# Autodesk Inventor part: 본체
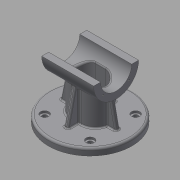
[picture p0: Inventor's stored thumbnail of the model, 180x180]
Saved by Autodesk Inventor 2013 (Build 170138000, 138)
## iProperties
Created: 2015-12
Part Number: 본체
Material: 일반
Document SubType Name: Modeling
Designer: mduedu
Density: 2.71 g/cm^3
Author: mduedu
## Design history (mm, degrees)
sketch "스케치1"
  geometry: L1 (45, 40)-(-45, 40); L2 (-45, 40)-(-45, -40); L3 (-45, -40)-(45, -40); L4 (45, -40)-(45, 40); L5 (45, 40)-(-45, -40); L6 (-45, 40)-(45, -40); 2 further points
  constraints: 12 end point, 2 midpoint, 2 parallel, 1 coincident, 1 horizontal, 1 perpendicular, 3 other
  dimensions: "d0" = 90 distance of L2.end L3.end; "d2" = 80 distance of L1.end L2.end
extrude "돌출1" new body sketch "스케치1" distance "d3" = 10; taper "d4" = 0 deg
sketch "스케치2"
  geometry: C1 r 32.5 at (80, 0); 1 further point
  constraints: 1 centre point
  dimensions: "d5" = 65 diameter of C1; "d116" = 80 distance of point (0, 0) C1.centre
extrude "돌출2" join sketch "스케치2" stored distance "d7" = 75; taper "d8" = 0 deg
sketch "스케치3"
  geometry: L1 (-27.5, -20)-(27.5, -20); L2 (27.5, -20)-(27.5, 20); L3 (27.5, 20)-(-27.5, 20); L4 (-27.5, 20)-(-27.5, -20); L5 (-27.5, -20)-(27.5, 20); L6 (27.5, -20)-(-27.5, 20); 1 further point
  constraints: 12 end point, 2 midpoint, 2 parallel, 1 horizontal, 1 perpendicular
  dimensions: "d9" = 55 distance of L2.end L3.end; "d11" = 40 distance of L1.end L2.end
extrude "돌출3" new body sketch "스케치3" stored distance "d12" = 75; taper "d13" = 0 deg
fillet "모깎기1"
fillet "모깎기2"
feature "결합1"
  node "솔리드2"
sketch "스케치4"
  geometry: L1 (-37.5, 47.5)-(37.5, 47.5) reference; L2 (32.5, 47.5)-(40.208, 10); L3 (37.5, 47.5)-(37.5, 112.5) reference; L4 (60.208, 0)-(60.208, 10) reference; L5 (60.208, 10)-(-60.208, 10) reference; 1 further point
  constraints: 2 end point, 2 point on line
  dimensions: "d15" = 5 distance from line of L2.start L3; "d117" = 20 distance from line of L2.end L4
sketch "스케치5"
  geometry: L1 (10, 35.208)-(58.179, 24.085); L2 (0, 60.208)-(10, 60.208) reference; L3 (10, -60.208)-(10, 60.208) reference; 2 further points
  constraints: 2 end point, 1 point on line, 2 other
  dimensions: "d118" = 25 distance from line of L1.start L2; "d119" = 77 deg angle of L1 L3
feature "리브1" dims "d19" = 1, "d20" = 6, "d21" = 0, "d22" = 0, "d23" = 1, "d24" = 1
feature "리브2" dims "d25" = 1, "d26" = 6, "d27" = 0, "d28" = 0, "d29" = 1, "d30" = 1
fillet "모깎기4" dims "d31" = 2
fillet "모깎기5" dims "d32" = 2
fillet "모깎기16" dims "d149" = 2
sketch "스케치6"
  geometry: L1 (0, 0)-(-32.88, 32.88); L2 (0, 0)-(-46.5, 0); A1 r 46.5 centre (0, 0) between (-32.88, 32.88) and (-46.5, 0); 5 further points
  constraints: 4 end point, 2 coincident, 2 point on circle, 1 centre point, 1 horizontal, 5 other
  dimensions: "d120" = 93 diameter of A1; "d122" = 45 deg angle of L1 L2; "d126" = 360 deg dimension on point (0, 0) point (-32.88, 32.88) (derived)
hole "구멍1" sketch "스케치6" at (-32.88, 32.88), (-32.88, -32.88), (32.88, -32.88), (32.88, 32.88) diameter "d34" = 7; stored, may be unused: countersink angle "d38" = 90 deg, drill point angle "d40" = 118 deg; dims "d35" = 6, "d36" = 12, "d37" = 3, "d39" = 8
fillet "모깎기13" dims "d131" = 3
hole "구멍2" diameter "d44" = 45; stored, may be unused: countersink angle "d48" = 90 deg, drill point angle "d50" = 118 deg; dims "d42" = 10, "d43" = 10, "d45" = 6, "d46" = 4, "d47" = 2, "d49" = 8
sketch "스케치7" dims "d52" = 26.5
  geometry: L1 (0, 0)-(32.5, 0); L2 (0, 0)-(22.981, 22.981); A1 r 32.5 centre (0, 0) between (32.5, 0) and (22.981, 22.981) reference; 3 further points
  constraints: 4 end point, 2 point on circle, 1 coincident, 1 horizontal, 1 point on line, 3 other
  dimensions: "d51" = 45 deg angle of L2 L1
hole "구멍3" sketch "스케치7" at (18.738, 18.738) diameter "d54" = 2.459; stored, may be unused: countersink angle "d58" = 90 deg, drill point angle "d60" = 118 deg; dims "d55" = 8, "d56" = 4, "d57" = 2, "d59" = 10
sketch "스케치9"
  geometry: L1 (-75, 82.5)-(75, 82.5); L2 (75, 82.5)-(75, 0); L3 (75, 0)-(-75, 0); L4 (-75, 0)-(-75, 82.5); C1 r 32.5 at (0, 0) reference; 2 further points
  constraints: 8 end point, 2 parallel, 1 coincident, 1 horizontal, 1 midpoint, 1 perpendicular
  dimensions: "d71" = 50 distance edge to line of C1 L1; "d148" = 150 distance of L1.start L1.end
extrude "돌출5" cut sketch "스케치9" stored distance "d73" = 0; taper "d74" = 0 deg
node "작업 평면1"
sketch "스케치10"
  geometry: L1 (-7.5, 15)-(7.5, 15); L2 (-7.5, -15)-(7.5, -15); A1 r 15 centre (-7.5, 0) between (-7.5, 15) and (-7.5, -15); A2 r 15 centre (7.5, 0) between (7.5, -15) and (7.5, 15); A3 r 20 centre (-7.5, 0) between (-7.5, 20) and (-26.977, 4.545) reference; A4 r 20 centre (7.5, 0) between (26.977, 4.545) and (7.5, 20) reference; 1 further point
  constraints: 7 point on circle, 4 end point, 4 tangent, 3 point on line, 2 centre point, 2 horizontal, 1 concentric
  dimensions: "d150" = 5 radial gap between concentric circles of A1 A3; "d151" = 5 radial gap between concentric circles of A2 A4
extrude "돌출6" cut sketch "스케치10" stored distance "d78" = 50; taper "d79" = 0 deg
fillet "모깎기10" dims "d80" = 3
sketch "스케치11"
  geometry: 2 further points
  constraints: 1 coincident
hole "구멍4" sketch "스케치11" at (0, 0) diameter "d81" = 11; stored, may be unused: countersink angle "d85" = 90 deg, drill point angle "d87" = 118 deg; dims "d82" = 8, "d83" = 40, "d84" = 10, "d86" = 10
sketch "스케치12"
  geometry: C1 r 12 at (0, 0); 1 further point
  constraints: 1 centre point, 1 coincident
  dimensions: "d88" = 24 diameter of C1
extrude "돌출7" cut sketch "스케치12" distance "d89" = 5; taper "d90" = 0 deg
chamfer "모따기1" distance "d91" = 1; stored, may be unused: second distance "d92" = 2, angle "d93" = 45 deg
fillet "모깎기11" dims "d94" = 0.5
fillet "모깎기12" dims "d115" = 0.3
node "작업 평면3"
sketch "스케치17"
  geometry: 2 further points
  constraints: 1 horizontal alignment, 1 other
  dimensions: "d154" = 3.5 distance of point (-3.5, 0) point (0, 0)
feature "엠보싱1" sketch "스케치17" dims "d155" = 0.5, "d156" = 0
node "솔리드1"
mirror "대칭1"
mirror "대칭2"
pattern_circular "원형 패턴1" dims angle "d62" = 360 deg
mirror "대칭3"
